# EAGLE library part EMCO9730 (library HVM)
EMCO Custom HV generator for IceCube.
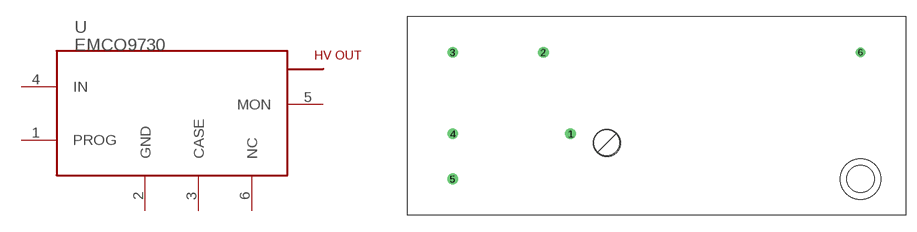
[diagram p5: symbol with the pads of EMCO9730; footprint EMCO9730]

Designator prefix U

## EMCO9730  [EMCO9730]
1  PROG  pas
2  GND  pas
3  CASE  pas
4  IN  pas
5  MON  pas
6  NC  nc

## Footprint EMCO9730 (pad centres in mm)
drill 1.016 round: 1 22.86,11.43; 2 19.05,22.86; 3 6.35,22.86; 4 6.35,11.43; 5 6.35,5.08
drill 0.813 round: 6 63.5,22.86
hole 3.81 at 63.5,5.08
hole 3.81 at 27.94,10.16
